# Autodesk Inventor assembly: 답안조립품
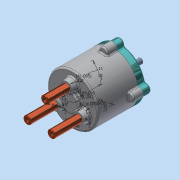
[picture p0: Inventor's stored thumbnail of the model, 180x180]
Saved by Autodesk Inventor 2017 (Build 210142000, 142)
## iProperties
Part Number: 답안조립품
Material: 일반
Document SubType Name: Assembly
Designer: MRC
Mass: 1236.64 g
Surface Area: 1770.13 cm^2
Volume: 433.789 cm^3
Density: 2.85079 g/cm^3
Author: MRC
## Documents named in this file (14)
- C:\Users\MRC\Desktop\610708V1004\답안조립품.iam
- C:\Users\MRC\Desktop\610708V1004\본체.ipt
- C:\Users\MRC\Desktop\610708V1004\가변스프링1.ipt
- C:\Users\MRC\Desktop\610708V1004\가변스프링2.ipt
- C:\Users\MRC\Desktop\610708V1004\가변스프링3.ipt
- C:\Users\MRC\Desktop\610708V1004\멈춤링 10 x 1.ipt
- C:\Users\MRC\Desktop\610708V1004\멈춤링 22 x 1.2.ipt
- C:\Users\MRC\Desktop\610708V1004\메인 축.ipt
- C:\Users\MRC\Desktop\610708V1004\베어링 NA 4900.ipt
- C:\Users\MRC\Desktop\610708V1004\볼트 M5.ipt
- C:\Users\MRC\Desktop\610708V1004\슬라이드 축.ipt
- C:\Users\MRC\Desktop\610708V1004\오일실.ipt
- C:\Users\MRC\Desktop\610708V1004\커버.ipt
- C:\Users\MRC\Desktop\610708V1004\판캠.ipt
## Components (3 placed, 3 different names)
1. 가변스프링3:1
2. 가변스프링1:1
3. 가변스프링2:1
